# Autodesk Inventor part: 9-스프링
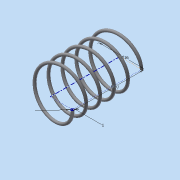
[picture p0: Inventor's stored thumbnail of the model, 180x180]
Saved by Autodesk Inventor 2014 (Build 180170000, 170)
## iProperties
Created: 2015-06
Part Number: 9-스프링
Material: 강철, 연강
Document SubType Name: Modeling
Designer: MYHOME
Density: 1 g/cm^3
Appearance: 강철
Author: MYHOME
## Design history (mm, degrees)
sketch "스케치1"
  geometry: L1 (0, 0)-(8, 0); L2 (8, 0)-(8, 14.5); L3 (8, 14.5)-(0, 14.5); L4 (0, 14.5)-(0, 0); C1 r 0.5 at (8, 0)
  constraints: 8 end point, 2 parallel, 1 centre point, 1 coincident, 1 horizontal, 1 perpendicular
  dimensions: "d0" = 1 diameter of C1; "d1" = 16 diameter of L2 L4; "d2" = 14.5 distance of L1.end L2.end (derived)
feature "코일1" sketch "스케치1" pitch "d3" = 10; turns "d5" = 5; dims "d4" = 14.5 (= d2), "d6" = 0, angle "d7" = 90 deg, angle "d8" = 90 deg, "d9" = 0, "d10" = 0
sketch "스케치2"
  geometry: L1 (-8.5, 0)-(-7.5, 0) reference; 1 further point
  constraints: 1 horizontal alignment
extrude "돌출1" cut sketch "스케치2" stored distance "d11" = 10; taper "d12" = 0 deg
node "작업 평면1"
sketch "스케치3"
  geometry: L1 (-7.5, 0)-(-8.5, 0) reference; 1 further point
  constraints: 1 horizontal alignment
extrude "돌출2" cut sketch "스케치3" stored distance "d14" = 10; taper "d15" = 0 deg
node "솔리드1"
node "절단 모서리 투영1"
node "절단 모서리 투영2"
other parameters: "d13" = 14.5 (= d2)
